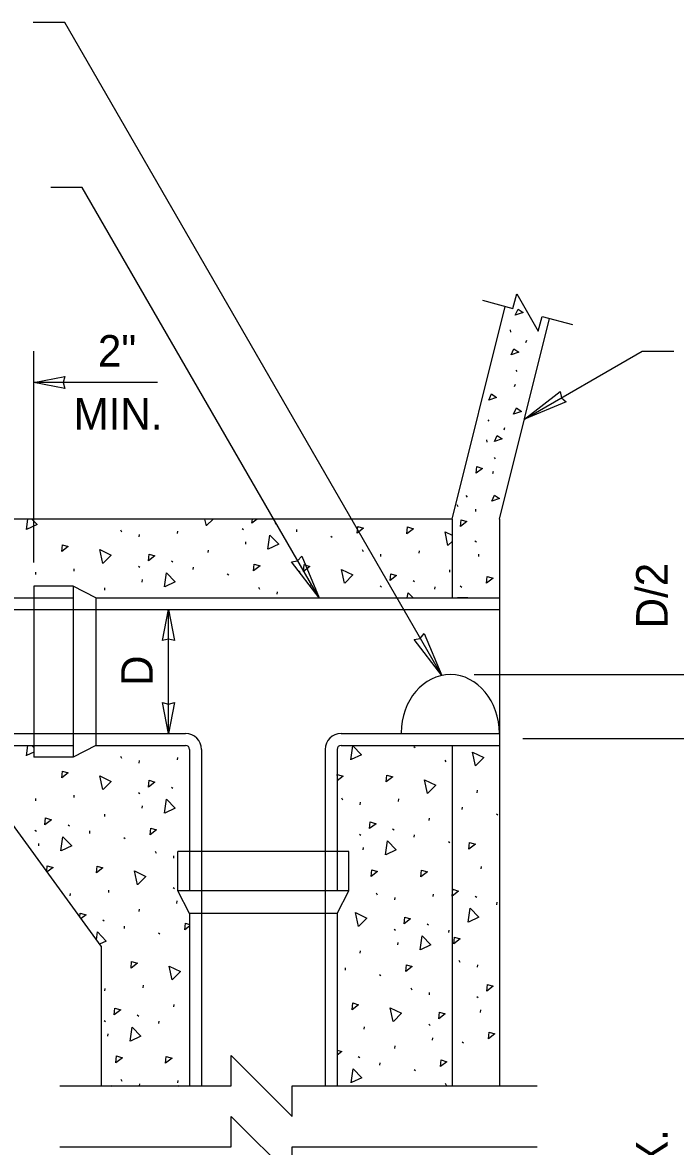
# Model space of a CAD drawing. Extents: x 99862 to 103151, y 100000 to 102076.
# Drawn here: x 101929 to 102261, y 100997 to 101568 of the extents above; entities that cross this region are included whole.
import ezdxf

# ---------------------------------------------------------------- set-up
doc = ezdxf.new("R2010")
doc.units = 0
for name, color, linetype in [('Level 1', 7, 'Continuous'), ('Level 15', 7, 'Continuous'), ('Level 17', 7, 'Continuous'), ('Level 19', 7, 'Continuous'), ('Level 20', 7, 'Continuous'), ('Level 6', 7, 'Continuous')]:
    doc.layers.add(name, color=color, linetype=linetype)

msp = doc.modelspace()

# ---------------------------------------------------------------- linework, layer by layer
at = {"layer": 'Level 1'}
for p, q in [((102147.16, 101315.98), (102174.19, 101424.09)), ((102171.16, 101315.98), (102196.68, 101418.04)), ((102171.16, 101315.98), (102171.16, 101275.98)), ((101954.47, 101281.98), (101934.47, 101281.98)), ((101934.47, 101281.98), (101934.47, 101194.98)), ((101954.47, 101281.98), (101954.47, 101194.98)), ((101965.92, 101275.98), (101954.47, 101281.98)), ((101726.16, 101275.98), (101934.47, 101275.98)), ((101965.92, 101275.98), (102171.16, 101275.98)), ((101965.92, 101275.98), (101965.92, 101200.98)), ((102155.17, 101275.98), (102149.84, 101275.98)), ((102171.16, 101275.98), (102171.16, 101200.98)), ((101726.16, 101200.98), (101934.47, 101200.98)), ((101965.92, 101200.98), (101954.47, 101194.98)), ((101965.92, 101200.98), (102011.66, 101200.98)), ((102013.66, 101198.98), (102013.66, 101146.98)), ((102088.66, 101198.98), (102088.66, 101146.98)), ((102090.66, 101200.98), (102171.16, 101200.98)), ((102171.16, 101200.98), (102171.16, 101027.93)), ((101954.47, 101194.98), (101934.47, 101194.98)), ((102007.66, 101126.98), (102007.66, 101146.98)), ((102094.66, 101146.98), (102007.66, 101146.98)), ((102094.66, 101126.98), (102094.66, 101146.98)), ((102013.66, 101115.53), (102007.66, 101126.98)), ((102094.66, 101126.98), (102007.66, 101126.98)), ((102088.66, 101115.53), (102094.66, 101126.98)), ((102013.66, 101115.53), (102013.66, 101027.93)), ((102088.66, 101115.53), (102013.66, 101115.53)), ((102088.66, 101115.53), (102088.66, 101027.93))]:
    msp.add_line(p, q, dxfattribs=at)
for centre, start, end in [((102011.66, 101198.98), 0, 90), ((102090.66, 101198.98), 90, 180)]:
    msp.add_arc(centre, 2, start, end, dxfattribs=at)
msp.add_ellipse((102146.16, 101206.98), major_axis=(0, -30), ratio=0.833333, start_param=1.570796, end_param=4.699405, dxfattribs=at)
at = {"layer": 'Level 15'}
for p, q in [((101950.2, 101568.44), (101934.2, 101568.44)), ((102141.83, 101236.53), (101950.2, 101568.44)), ((101959.08, 101484.53), (101943.08, 101484.53)), ((102079.48, 101275.98), (101959.08, 101484.53)), ((101934.47, 101293.98), (101934.47, 101401.45)), ((102183.87, 101366.83), (102243.82, 101401.44)), ((102243.82, 101401.44), (102259.82, 101401.44)), ((101997.27, 101385.45), (101934.47, 101385.45)), ((102002.92, 101206.98), (102002.92, 101269.98)), ((102158.34, 101236.98), (102280.7, 101236.98)), ((102183.16, 101204.48), (102280.7, 101204.48))]:
    msp.add_line(p, q, dxfattribs=at)
for points in [[(102162.51, 101427.24), (102177.96, 101423.08), (102179.97, 101430.56), (102190.9, 101411.58), (102192.91, 101419.05), (102208.36, 101414.89)], [(101947.66, 101027.93), (102034.76, 101027.93), (102034.76, 101043.41), (102065.74, 101012.44), (102065.74, 101027.93), (102190.41, 101027.93)], [(101947.66, 100996.95), (102034.76, 100996.95), (102034.76, 101012.44), (102065.74, 100981.47), (102065.74, 100996.95), (102190.41, 100996.95)]]:
    msp.add_lwpolyline(points, dxfattribs=at)
for points in [[(101934.47, 101385.45), (101950.19, 101388.53), (101949.46, 101385.45), (101950.19, 101382.36)], [(102183.87, 101366.83), (102202.15, 101380.83), (102202.73, 101377.72), (102205.14, 101375.66)], [(102079.48, 101275.98), (102065.49, 101294.26), (102068.6, 101294.84), (102070.66, 101297.25)], [(102002.92, 101269.98), (102006.01, 101254.26), (102002.92, 101254.99), (101999.84, 101254.26)], [(102141.83, 101236.53), (102127.83, 101254.81), (102130.94, 101255.38), (102133, 101257.79)], [(102002.92, 101206.98), (101999.84, 101222.71), (102002.92, 101221.98), (102006.01, 101222.71)]]:
    msp.add_lwpolyline(points, close=True, dxfattribs=at)
at = {"layer": 'Level 17'}
for p, q in [((102147.16, 101315.98), (101923.66, 101315.98)), ((102147.16, 101315.98), (102147.16, 101275.98)), ((102069.8, 101288.94), (102069.51, 101289.58)), ((102075.55, 101282.04), (102075.27, 101282.68)), ((102093.95, 101200.9), (102093.91, 101200.98)), ((102127.98, 101200.9), (102127.94, 101200.98)), ((102147.16, 101200.98), (102147.16, 101027.93)), ((101968.66, 101098.98), (101923.66, 101160.98)), ((101968.66, 101098.98), (101968.66, 101027.93)), ((101974.1, 101028.1), (101973.81, 101027.68)), ((102008.13, 101028.1), (102007.85, 101027.68))]:
    msp.add_line(p, q, dxfattribs=at)
at = {"layer": 'Level 19'}
for p, q in [((102176.65, 101412.14), (102176.8, 101411.02)), ((102184.59, 101405.77), (102185.06, 101406.91)), ((102179.56, 101391.7), (102180.08, 101390.97)), ((102178.86, 101383.48), (102179.33, 101384.62)), ((102165.27, 101366.51), (102165.78, 101365.78)), ((102173.52, 101361.47), (102173.98, 101362.61)), ((102164.56, 101356.29), (102164.72, 101355.17)), ((102168.48, 101347.4), (102169, 101346.67)), ((102167.78, 101339.18), (102168.25, 101340.31)), ((102154.19, 101327.95), (102154.71, 101327.22)), ((102149.58, 101323.47), (102150.08, 101322.46)), ((102159.12, 101319.91), (102159.21, 101321.14)), ((102040.31, 101311.21), (102041.03, 101310.68)), ((102057.13, 101313.97), (102057.85, 101313.44)), ((102068.14, 101309.58), (102068.22, 101310.8)), ((101978.51, 101310.56), (101979.01, 101309.55)), ((101988.05, 101307.01), (101988.13, 101308.23)), ((102007.55, 101308.68), (102007.63, 101309.9)), ((102085.46, 101307.42), (102086.18, 101306.89)), ((102158.76, 101304.97), (102159.48, 101304.44)), ((102023.11, 101299), (102023.2, 101300.22)), ((102042.22, 101303.19), (102042.31, 101304.42)), ((102101.35, 101300.51), (102101.85, 101299.5)), ((102130.39, 101298.64), (102130.48, 101299.86)), ((102004.5, 101294.81), (102005.22, 101294.28)), ((102110.89, 101296.96), (102110.97, 101298.19)), ((102160.68, 101296.95), (102160.76, 101298.17)), ((101935.43, 101287.85), (101935.51, 101289.07)), ((101954.93, 101289.53), (101955.01, 101290.75)), ((101987.69, 101292.06), (101988.41, 101291.53)), ((102015.51, 101290.43), (102015.6, 101291.65)), ((102032.84, 101288.27), (102033.56, 101287.74)), ((102145.95, 101288.96), (102146.04, 101290.18)), ((101989.6, 101284.04), (101989.69, 101285.26)), ((102127.35, 101284.77), (102128.07, 101284.24)), ((101970.49, 101279.85), (101970.57, 101281.07)), ((102048.73, 101281.36), (102049.23, 101280.35)), ((102058.27, 101277.81), (102058.35, 101279.03)), ((102077.77, 101279.48), (102077.86, 101280.71)), ((102110.53, 101282.02), (102111.25, 101281.49)), ((102138.36, 101280.39), (102138.44, 101281.61)), ((102151.29, 101282.02), (102152.01, 101281.49)), ((102127.62, 101200.46), (102128.34, 101199.93)), ((101978.51, 101195.56), (101979.01, 101194.55)), ((101988.05, 101192.01), (101988.13, 101193.23)), ((102007.55, 101193.68), (102007.63, 101194.9)), ((102143.51, 101193.56), (102144.01, 101192.55)), ((102004.5, 101179.81), (102005.22, 101179.28)), ((101935.43, 101172.85), (101935.51, 101174.07)), ((101954.93, 101174.53), (101955.01, 101175.75)), ((101987.69, 101177.06), (101988.41, 101176.53)), ((102090.88, 101174.4), (102091.38, 101173.39)), ((102119.93, 101172.53), (102120.01, 101173.75)), ((102159.91, 101176.95), (102160, 101178.17)), ((101989.6, 101169.04), (101989.69, 101170.26)), ((102100.43, 101170.85), (102100.51, 101172.07)), ((102152.32, 101168.38), (102152.4, 101169.6)), ((101970.49, 101164.85), (101970.57, 101166.07)), ((102135.49, 101162.85), (102135.57, 101164.07)), ((102169.64, 101166.22), (102170.36, 101165.69)), ((101935.06, 101157.91), (101935.78, 101157.38)), ((101951.88, 101160.66), (101952.6, 101160.13)), ((101962.89, 101156.27), (101962.98, 101157.5)), ((102116.88, 101158.66), (102117.6, 101158.13)), ((101936.98, 101149.89), (101937.07, 101151.11)), ((101980.22, 101154.11), (101980.94, 101153.58)), ((102100.06, 101155.91), (102100.78, 101155.38)), ((102127.89, 101154.27), (102127.98, 101155.5)), ((102145.22, 101152.11), (102145.94, 101151.58)), ((101996.1, 101147.21), (101996.6, 101146.2)), ((102101.98, 101147.89), (102102.07, 101149.11)), ((102005.65, 101143.66), (102005.73, 101144.88)), ((102161.95, 101138.28), (102162.04, 101139.51)), ((102005.28, 101128.71), (102006, 101128.18)), ((101953.02, 101124.5), (101953.11, 101125.73)), ((101972.52, 101126.18), (101972.61, 101127.4)), ((102108.48, 101126.05), (102108.98, 101125.04)), ((102118.02, 101122.5), (102118.11, 101123.73)), ((102137.52, 101124.18), (102137.61, 101125.4)), ((102158.9, 101124.42), (102159.62, 101123.89)), ((101988.08, 101116.5), (101988.17, 101117.72)), ((102007.2, 101120.69), (102007.29, 101121.91)), ((102169.92, 101120.03), (102170, 101121.25)), ((101969.48, 101112.31), (101970.2, 101111.78)), ((101980.49, 101107.93), (101980.57, 101109.15)), ((101997.81, 101105.76), (101998.53, 101105.24)), ((102117.66, 101107.56), (102118.38, 101107.03)), ((102134.48, 101110.31), (102135.2, 101109.78)), ((102145.49, 101105.93), (102145.57, 101107.15)), ((102119.58, 101099.54), (102119.66, 101100.76)), ((102100.46, 101095.34), (102100.55, 101096.57)), ((102092.87, 101086.77), (102092.95, 101087.99)), ((102150.51, 101091.81), (102151, 101090.8)), ((102160.05, 101088.26), (102160.13, 101089.48)), ((102110.19, 101084.61), (102110.91, 101084.08)), ((101970.62, 101076.15), (101970.7, 101077.38)), ((101990.12, 101077.83), (101990.21, 101079.05)), ((102126.08, 101077.71), (102126.58, 101076.7)), ((102135.62, 101074.15), (102135.7, 101075.38)), ((102159.68, 101073.31), (102160.41, 101072.78)), ((102005.68, 101068.15), (102005.77, 101069.37)), ((102161.6, 101065.29), (102161.69, 101066.52)), ((101970.26, 101061.21), (101970.98, 101060.68)), ((101987.08, 101063.96), (101987.8, 101063.43)), ((101998.09, 101059.58), (101998.17, 101060.8)), ((101972.17, 101053.19), (101972.26, 101054.41)), ((102102.5, 101056.68), (102102.58, 101057.9)), ((102135.26, 101059.21), (102135.98, 101058.68)), ((102118.06, 101046.99), (102118.15, 101048.22)), ((102137.17, 101051.19), (102137.26, 101052.41)), ((102152.21, 101050.37), (102152.94, 101049.84)), ((102099.45, 101042.81), (102100.17, 101042.28)), ((102110.46, 101038.42), (102110.55, 101039.65)), ((101978.68, 101031.36), (101979.18, 101030.35)), ((102007.72, 101029.48), (102007.8, 101030.7)), ((102127.79, 101036.26), (102128.51, 101035.73)), ((101988.23, 101027.93), (101988.3, 101029.03)), ((102143.68, 101029.36), (102144.18, 101028.35))]:
    msp.add_line(p, q, dxfattribs=at)
for points in [[(102179.25, 101419.59), (102180.64, 101422.74), (102183.19, 101420.95), (102179.25, 101419.59)], [(102177.18, 101399.47), (102178.58, 101402.62), (102181.12, 101400.83), (102177.18, 101399.47)], [(102165.8, 101376.54), (102167.19, 101379.69), (102169.74, 101377.9), (102165.8, 101376.54)], [(102178.41, 101369.41), (102179.81, 101372.56), (102182.35, 101370.78), (102178.41, 101369.41)], [(102168.63, 101355.44), (102170.03, 101358.59), (102172.57, 101356.8), (102168.63, 101355.44)], [(102159.31, 101339.28), (102159.64, 101342.71), (102162.62, 101341.81), (102159.31, 101339.28)], [(102167.34, 101325.11), (102168.73, 101328.26), (102171.27, 101326.48), (102167.34, 101325.11)], [(101930.67, 101310.73), (101931.4, 101315.98)], [(101933.45, 101315.98), (101936.11, 101313.24), (101930.79, 101310.78)], [(102022.2, 101312.65), (102021.48, 101315.98)], [(102025.57, 101315.98), (102022.3, 101312.72)], [(102045.37, 101313.98), (102045.57, 101315.98)], [(102048, 101315.98), (102045.37, 101313.98)], [(102098.84, 101308.85), (102099.17, 101312.28), (102102.15, 101311.38), (102098.84, 101308.85)], [(102124.15, 101308.6), (102124.49, 101312.03), (102127.46, 101311.13), (102124.15, 101308.6)], [(102151.34, 101312.25), (102151.67, 101315.69), (102154.65, 101314.79), (102151.34, 101312.25)], [(102053.51, 101300.69), (102054.5, 101307.79), (102058.95, 101303.2), (102053.63, 101300.73)], [(102145.04, 101302.6), (102143.54, 101309.62), (102147.16, 101307.86)], [(101948.68, 101299.49), (101949.02, 101302.92), (101951.99, 101302.02), (101948.68, 101299.49)], [(101969.58, 101293.49), (101968.07, 101300.51), (101973.83, 101297.71), (101969.68, 101293.57)], [(102147.16, 101304.69), (102145.14, 101302.68)], [(101992.75, 101294.83), (101993.08, 101298.26), (101996.06, 101297.36), (101992.75, 101294.83)], [(102000.89, 101281.54), (102001.88, 101288.64), (102006.33, 101284.05), (102001.01, 101281.58)], [(102046.21, 101289.7), (102046.55, 101293.12), (102049.52, 101292.22), (102046.21, 101289.7)], [(102071.52, 101289.45), (102071.86, 101292.88), (102074.83, 101291.98), (102071.52, 101289.45)], [(102092.42, 101283.45), (102090.92, 101290.46), (102096.67, 101287.66), (102092.52, 101283.53)], [(102115.59, 101284.78), (102115.93, 101288.21), (102118.9, 101287.31), (102115.59, 101284.78)], [(102164.67, 101283.45), (102165, 101286.88), (102167.98, 101285.98), (102164.67, 101283.45)], [(102124.36, 101275.98), (102124.72, 101278.6), (102127.25, 101275.98)], [(101930.67, 101195.73), (101931.4, 101200.98)], [(101934.47, 101197.48), (101930.79, 101195.78)], [(101933.45, 101200.98), (101934.47, 101199.93)], [(102095.67, 101193.73), (102096.66, 101200.84), (102101.11, 101196.24), (102095.79, 101193.78)], [(102159, 101190.6), (102157.5, 101197.61), (102163.26, 101194.81), (102159.1, 101190.68)], [(101948.68, 101184.49), (101949.02, 101187.92), (101951.99, 101187.02), (101948.68, 101184.49)], [(101969.58, 101178.49), (101968.07, 101185.51), (101973.83, 101182.71), (101969.68, 101178.57)], [(102088.66, 101185.69), (102088.7, 101186.17), (102091.68, 101185.27), (102088.66, 101182.96)], [(102113.68, 101182.49), (102114.02, 101185.92), (102116.99, 101185.02), (102113.68, 101182.49)], [(101992.75, 101179.83), (101993.08, 101183.26), (101996.06, 101182.36), (101992.75, 101179.83)], [(102134.58, 101176.49), (102133.07, 101183.51), (102138.83, 101180.71), (102134.68, 101176.57)], [(102000.89, 101166.54), (102001.88, 101173.64), (102006.33, 101169.05), (102001.01, 101166.58)], [(101940.12, 101160.67), (101940.46, 101164.1), (101943.44, 101163.2), (101940.12, 101160.67)], [(102105.12, 101158.67), (102105.46, 101162.1), (102108.44, 101161.2), (102105.12, 101158.67)], [(101993.59, 101155.54), (101993.93, 101158.97), (101996.9, 101158.07), (101993.59, 101155.54)], [(101948.27, 101147.38), (101949.25, 101154.49), (101953.71, 101149.89), (101948.38, 101147.43)], [(102113.27, 101145.38), (102114.25, 101152.49), (102118.71, 101147.89), (102113.38, 101145.43)], [(102155.7, 101148.25), (102156.04, 101151.68), (102159.01, 101150.78), (102155.7, 101148.25)], [(101941.03, 101137.05), (101941.3, 101139.82), (101944.28, 101138.92), (101941.32, 101136.66)], [(101966.28, 101136.14), (101966.62, 101139.57), (101969.59, 101138.67), (101966.28, 101136.14)], [(101987.17, 101130.14), (101985.67, 101137.16), (101991.43, 101134.36), (101987.27, 101130.22)], [(102105.97, 101134.39), (102106.3, 101137.82), (102109.28, 101136.92), (102105.97, 101134.39)], [(102131.28, 101134.14), (102131.62, 101137.57), (102134.59, 101136.67), (102131.28, 101134.14)], [(102147.15, 101124.43), (102147.49, 101127.86), (102150.46, 101126.96), (102147.15, 101124.43)], [(102155.29, 101111.14), (102156.28, 101118.24), (102160.73, 101113.65), (102155.41, 101111.18)], [(101957.87, 101113.85), (101958.06, 101115.75), (101961.04, 101114.85), (101958.53, 101112.94)], [(102099.55, 101108.99), (102098.05, 101116), (102103.81, 101113.2), (102099.65, 101109.07)], [(102122.72, 101110.32), (102123.06, 101113.75), (102126.04, 101112.85), (102122.72, 101110.32)], [(101966.31, 101102.22), (101966.85, 101106.14), (101971.3, 101101.54), (101967.93, 101099.98)], [(102011.19, 101107.19), (102011.52, 101110.62), (102013.66, 101109.98)], [(102013.66, 101109.08), (102011.19, 101107.19)], [(102130.86, 101097.04), (102131.85, 101104.14), (102136.3, 101099.54), (102130.98, 101097.08)], [(102147.99, 101100.14), (102148.33, 101103.57), (102151.3, 101102.67), (102147.99, 101100.14)], [(101983.88, 101087.79), (101984.21, 101091.22), (101987.19, 101090.32), (101983.88, 101087.79)], [(102004.77, 101081.79), (102003.27, 101088.81), (102009.03, 101086.01), (102004.87, 101081.87)], [(102123.56, 101086.04), (102123.9, 101089.47), (102126.88, 101088.57), (102123.56, 101086.04)], [(102164.74, 101076.08), (102165.08, 101079.51), (102168.06, 101078.61), (102164.74, 101076.08)], [(101975.32, 101063.97), (101975.66, 101067.41), (101978.63, 101066.5), (101975.32, 101063.97)], [(102096.25, 101066.64), (102096.59, 101070.07), (102099.56, 101069.17), (102096.25, 101066.64)], [(102117.15, 101060.64), (102115.65, 101067.66), (102121.4, 101064.86), (102117.25, 101060.72)], [(102140.32, 101061.97), (102140.66, 101065.41), (102143.63, 101064.5), (102140.32, 101061.97)], [(101983.46, 101050.69), (101984.45, 101057.79), (101988.9, 101053.19), (101983.58, 101050.73)], [(102165.59, 101051.8), (102165.92, 101055.22), (102168.9, 101054.32), (102165.59, 101051.8)], [(101976.16, 101039.69), (101976.5, 101043.12), (101979.47, 101042.22), (101976.16, 101039.69)], [(102001.47, 101039.44), (102001.81, 101042.88), (102004.78, 101041.97), (102001.47, 101039.44)], [(102088.66, 101046.06), (102091.01, 101045.35), (102088.66, 101043.56)], [(102095.84, 101029.53), (102096.83, 101036.64), (102101.28, 101032.04), (102095.96, 101029.58)], [(102141.16, 101037.69), (102141.5, 101041.12), (102144.47, 101040.22), (102141.16, 101037.69)]]:
    msp.add_lwpolyline(points, dxfattribs=at)
at = {"layer": 'Level 6'}
for p, q in [((101934.47, 101275.98), (101954.47, 101275.98)), ((101666.5, 101269.98), (102171.16, 101269.98)), ((101675.46, 101206.98), (102011.66, 101206.98)), ((102090.66, 101206.98), (102171.16, 101206.98)), ((101934.47, 101200.98), (101954.47, 101200.98)), ((102019.66, 101198.98), (102019.66, 101027.93)), ((102082.66, 101198.98), (102082.66, 101027.93)), ((102013.66, 101146.98), (102013.66, 101126.98)), ((102088.66, 101146.98), (102088.66, 101126.98))]:
    msp.add_line(p, q, dxfattribs=at)
for centre, start, end in [((102011.66, 101198.98), 0, 90), ((102090.66, 101198.98), 90, 180)]:
    msp.add_arc(centre, 8, start, end, dxfattribs=at)

# ---------------------------------------------------------------- texts
at = {"layer": 'Level 20'}
for s, rotation, p in [('2"', 360, (101967.06, 101393.55)), ('MIN.', 360, (101954.7, 101361.55)), ('D/2', 90, (102256.7, 101260.48)), ('D', 90, (101994.92, 101231.24)), ('20\' - 0" MAX.', 90, (102256.7, 100881.34))]:
    msp.add_text(s, height=16, rotation=rotation, dxfattribs=at).set_placement(p)

doc.saveas('drawing.dxf')
